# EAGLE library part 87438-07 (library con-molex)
Wire-to-Board 1.50mm (.059") Pitch Header - Right Angle, SMT, Shrouded Source: http://www.molex.com/product/micro/87438.html
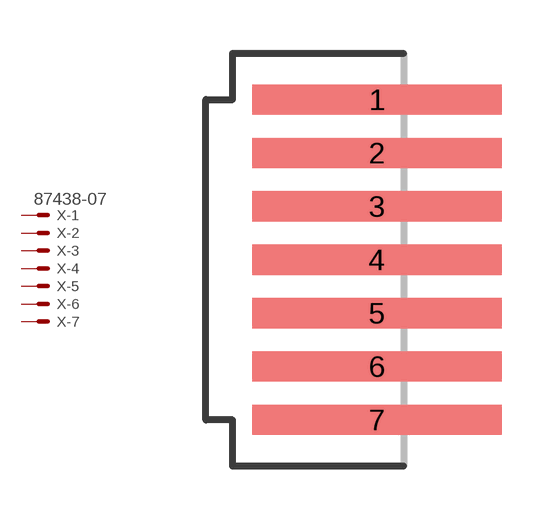
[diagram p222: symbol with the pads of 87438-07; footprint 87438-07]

Designator prefix X; gates -1=MV -2=M -3=M -4=M -5=M -6=M -7=M

## 87438-07 (MF: WALDOM/MOLEX; MPN: 87438-0733; OC_FARNELL: unknown; OC_NEWARK: 09J7507)  [87438-07]
1  -1:S  pas
2  -2:S  pas
3  -3:S  pas
4  -4:S  pas
5  -5:S  pas
6  -6:S  pas
7  -7:S  pas

## Footprint 87438-07 (pad centres in mm)
Wire-to-Board 1.50mm (.059") Pitch Header - Right Angle, SMT, Shrouded Source: http://www.molex.com/product/micro/87438.html
smd 7 x 0.85: 1 0,4.5; 2 0,3; 3 0,1.5; 4 0,0; 5 0,-1.5; 6 0,-3; 7 0,-4.5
